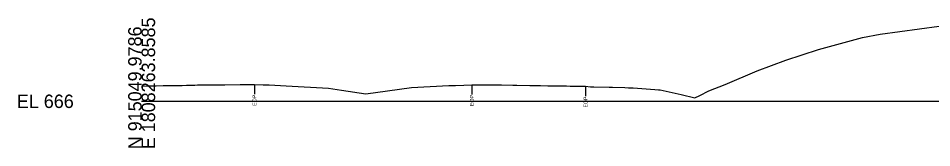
# Model space of a CAD drawing. Extents: x -26 to 403, y -10 to 8517.
# Drawn here: x -25.7 to 164.5, y 2490.3 to 2517.3 of the extents above; entities that cross this region are included whole.
import ezdxf

# ---------------------------------------------------------------- set-up
doc = ezdxf.new("R2010")
doc.units = 0
for name, color, linetype in [('Exist Cross Section Cell', 7, 'Continuous'), ('Exist XS Ground Line', 7, 'Continuous'), ('Old_Level_10', 7, 'Continuous')]:
    doc.layers.add(name, color=color, linetype=linetype)

msp = doc.modelspace()

# ---------------------------------------------------------------- linework, layer by layer
at = {"layer": 'Exist Cross Section Cell'}
msp.add_line((0, 2500), (200, 2500), dxfattribs=at)
at = {"layer": 'Exist XS Ground Line'}
msp.add_lwpolyline([(0, 2503.18), (1.27, 2503.21), (3.05, 2503.25), (4.47, 2503.28), (4.85, 2503.29), (5.33, 2503.3), (6.63, 2503.32), (7.69, 2503.31), (8.43, 2503.32), (9.37, 2503.34), (11.08, 2503.39), (11.63, 2503.4), (12.76, 2503.42), (13.27, 2503.42), (13.71, 2503.43), (14.06, 2503.44), (17.32, 2503.46), (20.51, 2503.48), (21.3, 2503.49), (23.48, 2503.51), (25.3, 2503.41), (26.21, 2503.4), (26.55, 2503.4), (27.7, 2503.39), (30.11, 2503.24), (38.89, 2502.71), (41.62, 2502.3), (46.69, 2501.57), (51.22, 2502.19), (56.19, 2502.9), (63.94, 2503.28), (64.83, 2503.32), (65.34, 2503.32), (67.11, 2503.36), (68.77, 2503.46), (69.3, 2503.46), (70.66, 2503.44), (71.76, 2503.43), (72.44, 2503.42), (73.28, 2503.41), (74.93, 2503.4), (77.31, 2503.37), (77.77, 2503.36), (78.15, 2503.36), (80.81, 2503.31), (81.38, 2503.3), (83.09, 2503.27), (84.57, 2503.25), (84.89, 2503.24), (85.29, 2503.24), (86.66, 2503.22), (87.78, 2503.21), (88.44, 2503.2), (89.26, 2503.18), (90.99, 2503.15), (92.44, 2503.14), (93.49, 2503.05), (94.19, 2503.02), (97.39, 2502.94), (98.05, 2502.92), (100.6, 2502.87), (101.39, 2502.84), (102.37, 2502.82), (105.96, 2502.53), (106.9, 2502.46), (107.63, 2502.41), (108.01, 2502.38), (112.32, 2501.39), (115.18, 2500.74), (116.24, 2501.2), (118.12, 2502.21), (121.53, 2503.49), (128.17, 2506.38), (134.12, 2508.6), (140.98, 2510.8), (150.11, 2513.29), (153.79, 2513.99), (166.1, 2515.65)], dxfattribs=at)
at = {"layer": 'Old_Level_10'}
for p, q in [((23.48, 2503.51), (23.48, 2501.46)), ((68.77, 2503.46), (68.77, 2501.41)), ((92.44, 2503.14), (92.44, 2501.09))]:
    msp.add_line(p, q, dxfattribs=at)

# ---------------------------------------------------------------- texts
at = {"layer": 'Exist Cross Section Cell'}
for s, p in [('E 1808263.8585', (2.8, 2490)), ('N 915049.9786', (0, 2490))]:
    msp.add_text(s, height=2.8, rotation=90, dxfattribs=at).set_placement(p)
msp.add_text('EL 666', height=2.8, dxfattribs=at).set_placement((-26, 2498.6))
at = {"layer": 'Old_Level_10'}
for p in [(23.88, 2499.07), (69.16, 2499.02), (92.84, 2498.69)]:
    msp.add_text('EOP', height=0.787, rotation=90, dxfattribs=at).set_placement(p)

doc.saveas('drawing.dxf')
